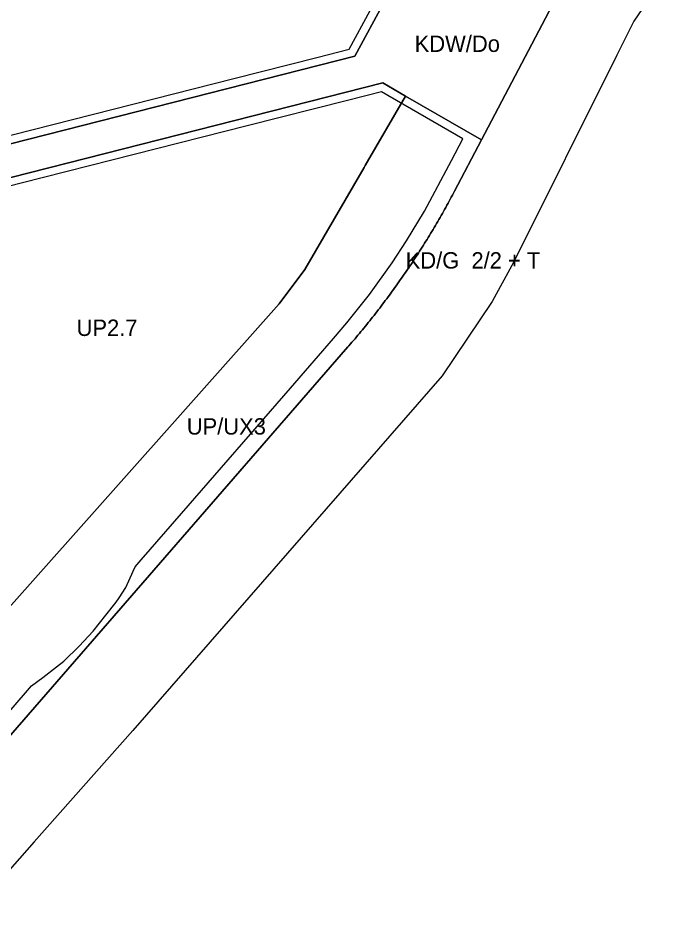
# Model space of a CAD drawing. Extents: x -297746 to -295403, y 27112 to 28877.
# Drawn here: x -296657 to -296256, y 27359 to 27910 of the extents above; entities that cross this region are included whole.
import ezdxf

# ---------------------------------------------------------------- set-up
doc = ezdxf.new("R2010")
doc.units = 0
for name, color, linetype in [('linie_rozgraniczajace', 7, 'Continuous'), ('linie_zabudowy_nieprzekraczalne', 7, 'Continuous'), ('linie_zabudowy_obowiazujace', 7, 'Continuous'), ('oznaczenia_przeznaczen', 7, 'Continuous')]:
    doc.layers.add(name, color=color, linetype=linetype)

msp = doc.modelspace()

# ---------------------------------------------------------------- linework, layer by layer
at = {"layer": 'linie_rozgraniczajace'}
for points in [[(-296676.764, 28119.432), (-296648.438, 28138.524), (-296433.475, 27919.768), (-296451.602, 27886.266), (-296706.72, 27821.429)], [(-296255.594, 27945.248), (-296281.298, 27907.627), (-296291.684, 27886.943), (-296354.522, 27760.921), (-296367.796, 27736.703), (-296398.222, 27691.308), (-296587.084, 27474.778), (-296647.178, 27406.935), (-296689.426, 27359.239)], [(-296706.72, 27821.429), (-296451.602, 27886.266), (-296433.475, 27919.768)], [(-296331.038, 27917.337), (-296374.255, 27835.235), (-296420.556, 27861.932), (-296434.505, 27869.975), (-296706.45, 27800.862)], [(-296427.094, 27745.146), (-296426.27, 27746.295), (-296425.45, 27747.447), (-296424.632, 27748.602), (-296423.819, 27749.758), (-296423.008, 27750.917), (-296422.201, 27752.078), (-296421.397, 27753.242), (-296420.596, 27754.407), (-296419.798, 27755.575), (-296419.004, 27756.745), (-296418.213, 27757.918), (-296417.426, 27759.092), (-296416.642, 27760.269), (-296415.861, 27761.448), (-296415.083, 27762.63), (-296414.309, 27763.813), (-296413.538, 27764.999), (-296412.771, 27766.187), (-296412.007, 27767.377), (-296411.246, 27768.569), (-296410.489, 27769.763), (-296409.735, 27770.96), (-296408.984, 27772.158), (-296408.237, 27773.359), (-296407.493, 27774.562), (-296406.753, 27775.767), (-296406.016, 27776.974), (-296405.282, 27778.183), (-296404.552, 27779.394), (-296403.825, 27780.607), (-296403.102, 27781.822), (-296402.382, 27783.04), (-296401.666, 27784.259), (-296400.953, 27785.48), (-296400.244, 27786.704), (-296399.538, 27787.929), (-296398.835, 27789.157), (-296398.136, 27790.386), (-296397.44, 27791.617), (-296396.748, 27792.851), (-296396.06, 27794.086), (-296395.374, 27795.323), (-296394.693, 27796.562), (-296394.015, 27797.803), (-296393.34, 27799.046), (-296392.669, 27800.291), (-296392.001, 27801.538), (-296391.337, 27802.786), (-296390.677, 27804.037), (-296374.255, 27835.235), (-296331.038, 27917.337)], [(-296708.605, 27498.319), (-296497.72, 27735.144), (-296482.154, 27756.115), (-296445.951, 27818.307), (-296445.171, 27819.646), (-296420.556, 27861.932), (-296374.255, 27835.235), (-296390.677, 27804.037), (-296391.337, 27802.786), (-296392.001, 27801.538), (-296392.669, 27800.291), (-296393.34, 27799.046), (-296394.015, 27797.803), (-296394.693, 27796.562), (-296395.374, 27795.323), (-296396.06, 27794.086), (-296396.748, 27792.851), (-296397.44, 27791.617), (-296398.136, 27790.386), (-296398.835, 27789.157), (-296399.538, 27787.929), (-296400.244, 27786.704), (-296400.953, 27785.48), (-296401.666, 27784.259), (-296402.382, 27783.04), (-296403.102, 27781.822), (-296403.825, 27780.607), (-296404.552, 27779.394), (-296405.282, 27778.183), (-296406.016, 27776.974), (-296406.753, 27775.767), (-296407.493, 27774.562), (-296408.237, 27773.359), (-296408.984, 27772.158), (-296409.735, 27770.96), (-296410.489, 27769.763), (-296411.246, 27768.569), (-296412.007, 27767.377), (-296412.771, 27766.187), (-296413.538, 27764.999), (-296414.309, 27763.813), (-296415.083, 27762.63), (-296415.861, 27761.448), (-296416.642, 27760.269), (-296417.426, 27759.092), (-296418.213, 27757.918), (-296419.004, 27756.745), (-296419.798, 27755.575), (-296420.596, 27754.407), (-296421.397, 27753.242), (-296422.201, 27752.078), (-296423.008, 27750.917), (-296423.819, 27749.758), (-296424.632, 27748.602), (-296425.45, 27747.447), (-296426.27, 27746.295), (-296427.094, 27745.146), (-296427.921, 27743.999), (-296428.751, 27742.854), (-296429.584, 27741.711), (-296430.421, 27740.571), (-296431.261, 27739.433), (-296432.104, 27738.298), (-296432.95, 27737.165), (-296433.799, 27736.034), (-296434.652, 27734.906), (-296435.508, 27733.78), (-296436.367, 27732.656), (-296437.229, 27731.535), (-296438.095, 27730.417), (-296438.963, 27729.301), (-296439.835, 27728.187), (-296440.71, 27727.076), (-296441.588, 27725.967), (-296442.469, 27724.861), (-296443.353, 27723.757), (-296444.24, 27722.656), (-296445.131, 27721.558), (-296446.024, 27720.461), (-296446.921, 27719.368), (-296447.821, 27718.277), (-296448.724, 27717.188), (-296449.629, 27716.102), (-296450.538, 27715.019), (-296451.45, 27713.938), (-296452.366, 27712.86), (-296453.284, 27711.784), (-296454.205, 27710.711), (-296455.129, 27709.641), (-296455.785, 27708.884), (-296664.406, 27468.917)], [(-296664.406, 27468.917), (-296455.785, 27708.884), (-296455.129, 27709.641), (-296454.205, 27710.711), (-296453.284, 27711.784), (-296452.366, 27712.86), (-296451.45, 27713.938), (-296450.538, 27715.019), (-296449.629, 27716.102), (-296448.724, 27717.188), (-296447.821, 27718.277), (-296446.921, 27719.368), (-296446.024, 27720.461), (-296445.131, 27721.558), (-296444.24, 27722.656), (-296443.353, 27723.757), (-296442.469, 27724.861), (-296441.588, 27725.967), (-296440.71, 27727.076), (-296439.835, 27728.187), (-296438.963, 27729.301), (-296438.095, 27730.417), (-296437.229, 27731.535), (-296436.367, 27732.656), (-296435.508, 27733.78), (-296434.652, 27734.906), (-296433.799, 27736.034), (-296432.95, 27737.165), (-296432.104, 27738.298), (-296431.261, 27739.433), (-296430.421, 27740.571), (-296429.584, 27741.711), (-296428.751, 27742.854), (-296427.921, 27743.999), (-296427.094, 27745.146)]]:
    msp.add_lwpolyline(points, dxfattribs=at)
msp.add_lwpolyline([(-296708.605, 27498.319), (-296712.625, 27509.58), (-296716.282, 27788.045), (-296706.45, 27800.862), (-296434.505, 27869.975), (-296420.556, 27861.932), (-296445.171, 27819.646), (-296445.951, 27818.307), (-296482.154, 27756.115), (-296497.72, 27735.144)], close=True, dxfattribs=at)
at = {"layer": 'linie_zabudowy_nieprzekraczalne'}
for points in [[(-296649.741, 28125.587), (-296679.465, 28105.72), (-296681.763, 28104.411), (-296712.278, 28086.739), (-296715.138, 28081.914), (-296714.191, 28009.758), (-296712.447, 27877.015), (-296711.852, 27831.672), (-296705.598, 27826.874), (-296660.684, 27838.289), (-296525.454, 27872.657), (-296474.728, 27885.549), (-296454.954, 27890.574), (-296442.117, 27914.3), (-296453.116, 27925.493)], [(-296392.59, 27822.729), (-296385.574, 27835.994), (-296435.239, 27864.631), (-296456.082, 27859.334), (-296517.287, 27843.779), (-296655.075, 27808.761), (-296703.535, 27796.445)], [(-296464.57, 27714.158), (-296456.348, 27723.657), (-296442.623, 27740.942), (-296428.729, 27760.227), (-296419.979, 27773.59)], [(-296673.896, 27473.241), (-296648.812, 27502.094), (-296641.856, 27507.184), (-296633.681, 27513.69), (-296629.208, 27517.256), (-296619.775, 27526.353), (-296611.204, 27535.44), (-296603.433, 27545.211), (-296597.254, 27553.259), (-296595.358, 27555.751), (-296591.241, 27562.148), (-296586.724, 27572.142), (-296585.692, 27574.699), (-296581.888, 27579.074)]]:
    msp.add_lwpolyline(points, dxfattribs=at)
at = {"layer": 'linie_zabudowy_obowiazujace'}
for points in [[(-296419.979, 27773.59), (-296408.952, 27791.796), (-296392.592, 27822.726)], [(-296581.888, 27579.074), (-296557.346, 27607.303), (-296490.828, 27683.817), (-296464.57, 27714.158)]]:
    msp.add_lwpolyline(points, dxfattribs=at)

# ---------------------------------------------------------------- texts
at = {"layer": 'oznaczenia_przeznaczen'}
for s, p in [('KDW/Do', (-296415.033, 27888.914)), ('KD/G  2/2 + T', (-296420.515, 27756.726)), ('UP2.7', (-296621.337, 27715.605)), ('UP/UX3', (-296554.112, 27655.416))]:
    msp.add_text(s, height=10, dxfattribs=at).set_placement(p)

doc.saveas('drawing.dxf')
